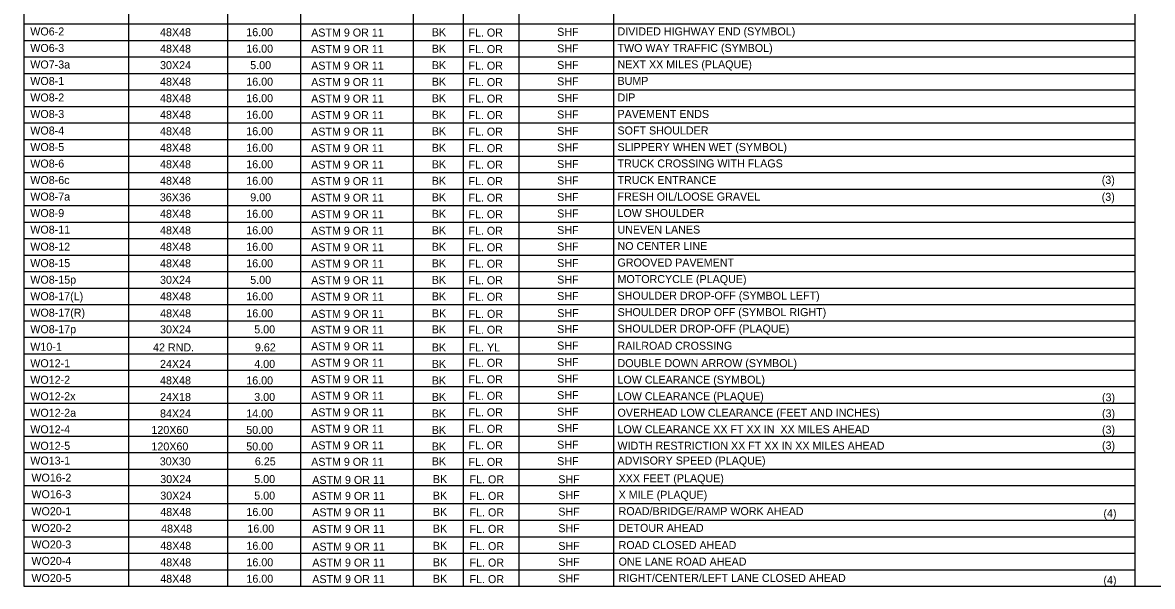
# Model space of a CAD drawing. Extents: x -439.1 to -407.9, y -458.1 to -437.7.
# Drawn here: x -439.13 to -418.9, y -458.05 to -447.95 of the extents above; entities that cross this region are included whole.
import ezdxf

# ---------------------------------------------------------------- set-up
doc = ezdxf.new("R2010")
doc.units = 0
for name, color, linetype in [('Draft_Named_Boundary', 7, 'Continuous'), ('Level 4', 7, 'Continuous'), ('Level 45', 7, 'Continuous')]:
    doc.layers.add(name, color=color, linetype=linetype)

msp = doc.modelspace()

# ---------------------------------------------------------------- linework, layer by layer
at = {"layer": 'Draft_Named_Boundary'}
msp.add_lwpolyline([(-439.109, -458.051), (-407.859, -458.051), (-407.859, -437.676), (-439.109, -437.676)], close=True, dxfattribs=at)
at = {"layer": 'Level 4'}
for p, q in [((-439.109, -437.676), (-439.109, -458.051)), ((-419.212, -437.676), (-419.212, -458.051)), ((-437.233, -438.806), (-437.233, -458.051)), ((-435.462, -438.806), (-435.462, -458.051)), ((-434.152, -438.806), (-434.152, -458.051)), ((-432.136, -438.806), (-432.136, -458.051)), ((-431.24, -438.806), (-431.24, -458.051)), ((-430.244, -438.806), (-430.244, -458.051)), ((-428.547, -438.806), (-428.547, -458.051)), ((-439.109, -447.976), (-419.212, -447.976)), ((-439.109, -448.272), (-419.212, -448.272)), ((-439.109, -448.568), (-419.212, -448.568)), ((-439.109, -448.864), (-419.212, -448.864)), ((-439.109, -449.159), (-419.212, -449.159)), ((-439.109, -449.455), (-419.212, -449.455)), ((-439.109, -449.751), (-419.212, -449.751)), ((-439.109, -450.047), (-419.212, -450.047)), ((-439.109, -450.343), (-419.212, -450.343)), ((-439.109, -450.638), (-419.212, -450.638)), ((-439.109, -450.934), (-419.212, -450.934)), ((-439.109, -451.23), (-419.212, -451.23)), ((-439.109, -451.526), (-419.212, -451.526)), ((-439.109, -451.822), (-419.212, -451.822)), ((-439.109, -452.117), (-419.212, -452.117)), ((-439.109, -452.413), (-419.212, -452.413)), ((-439.109, -452.709), (-419.212, -452.709)), ((-439.109, -453.005), (-419.212, -453.005)), ((-439.109, -453.298), (-419.212, -453.298)), ((-439.109, -453.591), (-419.212, -453.591)), ((-439.109, -453.885), (-419.212, -453.885)), ((-439.109, -454.178), (-419.212, -454.178)), ((-439.109, -454.474), (-419.212, -454.474)), ((-439.109, -454.769), (-419.212, -454.769)), ((-439.109, -455.065), (-419.212, -455.065)), ((-439.109, -455.361), (-419.212, -455.361)), ((-439.109, -455.656), (-419.212, -455.656)), ((-439.109, -455.952), (-419.212, -455.952)), ((-439.109, -456.248), (-419.212, -456.248)), ((-439.109, -456.571), (-419.212, -456.571)), ((-439.129, -456.867), (-419.232, -456.867)), ((-439.109, -457.163), (-419.212, -457.163)), ((-439.109, -457.458), (-419.212, -457.458)), ((-439.109, -457.754), (-419.212, -457.754)), ((-439.109, -458.051), (-419.212, -458.051))]:
    msp.add_line(p, q, dxfattribs=at)

# ---------------------------------------------------------------- texts
for s, height, p in [('WO6-2', 0.1433, (-438.991, -448.183)), ('ASTM 9 OR 11', 0.14328, (-433.962, -448.203)), ('BK', 0.1433, (-431.802, -448.196)), ('FL. OR', 0.1433, (-431.146, -448.203)), ('SHF', 0.1433, (-429.557, -448.19)), ('DIVIDED HIGHWAY END (SYMBOL)', 0.14328, (-428.477, -448.182)), ('WO6-3', 0.1433, (-438.991, -448.479)), ('ASTM 9 OR 11', 0.14328, (-433.962, -448.499)), ('BK', 0.1433, (-431.802, -448.491)), ('FL. OR', 0.1433, (-431.146, -448.499)), ('SHF', 0.1433, (-429.557, -448.486)), ('TWO WAY TRAFFIC (SYMBOL)', 0.14328, (-428.477, -448.478)), ('WO7-3a', 0.1433, (-438.991, -448.775)), ('ASTM 9 OR 11', 0.14328, (-433.962, -448.795)), ('BK', 0.1433, (-431.802, -448.787)), ('FL. OR', 0.1433, (-431.146, -448.795)), ('SHF', 0.1433, (-429.557, -448.782)), ('NEXT XX MILES (PLAQUE)', 0.14328, (-428.477, -448.773)), ('WO8-1 ', 0.1433, (-438.991, -449.071)), ('ASTM 9 OR 11', 0.14328, (-433.962, -449.09)), ('BK', 0.1433, (-431.802, -449.083)), ('FL. OR', 0.1433, (-431.146, -449.091)), ('SHF', 0.1433, (-429.557, -449.078)), ('BUMP', 0.1433, (-428.477, -449.069)), ('WO8-2 ', 0.1433, (-438.991, -449.366)), ('ASTM 9 OR 11', 0.14328, (-433.962, -449.386)), ('BK', 0.1433, (-431.802, -449.379)), ('FL. OR', 0.1433, (-431.146, -449.386)), ('SHF', 0.1433, (-429.557, -449.374)), ('DIP', 0.1433, (-428.477, -449.365)), ('WO8-3', 0.1433, (-438.991, -449.662)), ('ASTM 9 OR 11', 0.14328, (-433.962, -449.682)), ('BK', 0.1433, (-431.802, -449.675)), ('FL. OR', 0.1433, (-431.146, -449.682)), ('SHF', 0.1433, (-429.557, -449.67)), ('PAVEMENT ENDS', 0.14328, (-428.477, -449.661)), ('WO8-4 ', 0.1433, (-438.991, -449.958)), ('ASTM 9 OR 11', 0.14328, (-433.962, -449.978)), ('BK', 0.1433, (-431.802, -449.97)), ('FL. OR', 0.1433, (-431.146, -449.978)), ('SHF', 0.1433, (-429.557, -449.965)), ('SOFT SHOULDER', 0.14328, (-428.477, -449.957)), ('SLIPPERY WHEN WET (SYMBOL) ', 0.14328, (-428.477, -450.253)), ('WO8-5 ', 0.1433, (-438.991, -450.254)), ('ASTM 9 OR 11', 0.14328, (-433.962, -450.274)), ('BK', 0.1433, (-431.802, -450.266)), ('FL. OR', 0.1433, (-431.146, -450.274)), ('SHF', 0.1433, (-429.557, -450.261)), ('WO8-6 ', 0.1433, (-438.991, -450.55)), ('ASTM 9 OR 11', 0.14328, (-433.962, -450.569)), ('BK', 0.1433, (-431.802, -450.562)), ('FL. OR', 0.1433, (-431.146, -450.57)), ('SHF', 0.1433, (-429.557, -450.557)), ('TRUCK CROSSING WITH FLAGS', 0.14328, (-428.477, -450.548)), ('WO8-6c', 0.1433, (-438.991, -450.845)), ('BK', 0.1433, (-431.802, -450.858)), ('SHF', 0.1433, (-429.557, -450.853)), ('TRUCK ENTRANCE ', 0.14328, (-428.477, -450.844)), ('(3)', 0.1433, (-419.806, -450.842)), ('ASTM 9 OR 11', 0.14328, (-433.962, -450.865)), ('FL. OR', 0.1433, (-431.146, -450.865)), ('WO8-7a ', 0.1433, (-438.991, -451.141)), ('ASTM 9 OR 11', 0.14328, (-433.962, -451.161)), ('BK', 0.1433, (-431.802, -451.154)), ('FL. OR', 0.1433, (-431.146, -451.161)), ('SHF', 0.1433, (-429.557, -451.149)), ('FRESH OIL/LOOSE GRAVEL', 0.14328, (-428.477, -451.14)), ('(3)', 0.1433, (-419.807, -451.146)), ('WO8-9', 0.1433, (-438.991, -451.437)), ('ASTM 9 OR 11', 0.14328, (-433.962, -451.457)), ('BK', 0.1433, (-431.802, -451.45)), ('FL. OR', 0.1433, (-431.146, -451.457)), ('SHF', 0.1433, (-429.557, -451.444)), ('LOW SHOULDER', 0.14328, (-428.477, -451.436)), ('WO8-11', 0.1433, (-438.991, -451.733)), ('ASTM 9 OR 11', 0.14328, (-433.962, -451.753)), ('BK', 0.1433, (-431.802, -451.745)), ('FL. OR', 0.1433, (-431.146, -451.753)), ('SHF', 0.1433, (-429.557, -451.74)), ('UNEVEN LANES', 0.14328, (-428.477, -451.732)), ('WO8-12', 0.1433, (-438.991, -452.038)), ('ASTM 9 OR 11', 0.14328, (-433.962, -452.049)), ('BK', 0.1433, (-431.802, -452.041)), ('FL. OR', 0.1433, (-431.146, -452.049)), ('SHF', 0.1433, (-429.557, -452.036)), ('NO CENTER LINE', 0.14328, (-428.477, -452.027)), ('WO8-15', 0.1433, (-438.991, -452.334)), ('ASTM 9 OR 11', 0.14328, (-433.962, -452.344)), ('BK', 0.1433, (-431.802, -452.337)), ('FL. OR', 0.1433, (-431.146, -452.344)), ('SHF', 0.1433, (-429.557, -452.332)), ('GROOVED PAVEMENT', 0.14328, (-428.477, -452.323)), ('WO8-15p', 0.1433, (-438.991, -452.63)), ('ASTM 9 OR 11', 0.14328, (-433.962, -452.64)), ('BK', 0.1433, (-431.802, -452.633)), ('FL. OR', 0.1433, (-431.146, -452.64)), ('SHF', 0.1433, (-429.557, -452.628)), ('MOTORCYCLE (PLAQUE)', 0.14328, (-428.477, -452.619)), ('WO8-17(L)', 0.1433, (-438.991, -452.926)), ('ASTM 9 OR 11', 0.14328, (-433.962, -452.936)), ('BK', 0.1433, (-431.802, -452.929)), ('FL. OR', 0.1433, (-431.146, -452.936)), ('SHF', 0.1433, (-429.557, -452.923)), ('SHOULDER DROP-OFF (SYMBOL LEFT)', 0.14328, (-428.477, -452.915)), ('WO8-17(R)', 0.1433, (-438.99, -453.221)), ('ASTM 9 OR 11', 0.14328, (-433.961, -453.242)), ('BK', 0.1433, (-431.8, -453.233)), ('FL. OR', 0.1433, (-431.144, -453.242)), ('SHF', 0.1433, (-429.556, -453.229)), ('SHOULDER DROP OFF (SYMBOL RIGHT)', 0.14328, (-428.476, -453.211)), ('WO8-17p', 0.1433, (-438.991, -453.517)), ('ASTM 9 OR 11', 0.14328, (-433.962, -453.527)), ('BK', 0.1433, (-431.802, -453.52)), ('FL. OR', 0.1433, (-431.146, -453.527)), ('SHF', 0.1433, (-429.557, -453.515)), ('SHOULDER DROP-OFF (PLAQUE)', 0.14328, (-428.477, -453.506)), ('W10-1', 0.1433, (-438.991, -453.831)), ('ASTM 9 OR 11', 0.14328, (-433.962, -453.823)), ('BK', 0.1433, (-431.802, -453.843)), ('FL. YL', 0.1433, (-431.142, -453.843)), ('SHF', 0.1433, (-429.557, -453.81)), ('RAILROAD CROSSING', 0.14328, (-428.477, -453.814)), ('WO12-1', 0.1433, (-438.991, -454.127)), ('ASTM 9 OR 11', 0.14328, (-433.962, -454.119)), ('BK', 0.1433, (-431.802, -454.139)), ('FL. OR', 0.1433, (-431.146, -454.119)), ('SHF', 0.1433, (-429.557, -454.106)), ('DOUBLE DOWN ARROW (SYMBOL)', 0.14328, (-428.477, -454.125)), ('WO12-2 ', 0.1433, (-438.991, -454.423)), ('ASTM 9 OR 11', 0.14328, (-433.962, -454.414)), ('BK', 0.1433, (-431.802, -454.435)), ('FL. OR', 0.1433, (-431.146, -454.415)), ('SHF', 0.1433, (-429.557, -454.402)), ('LOW CLEARANCE (SYMBOL)', 0.14328, (-428.477, -454.421)), ('SHF', 0.1433, (-429.557, -454.698)), ('WO12-2x', 0.1433, (-438.991, -454.718)), ('ASTM 9 OR 11', 0.14328, (-433.962, -454.71)), ('BK', 0.1433, (-431.802, -454.731)), ('FL. OR', 0.1433, (-431.146, -454.71)), ('LOW CLEARANCE (PLAQUE)', 0.14328, (-428.477, -454.717)), ('(3)', 0.1433, (-419.802, -454.738)), ('WO12-2a', 0.1433, (-438.991, -455.014)), ('ASTM 9 OR 11', 0.14328, (-433.962, -455.006)), ('BK', 0.1433, (-431.802, -455.027)), ('FL. OR', 0.1433, (-431.146, -455.006)), ('SHF', 0.1433, (-429.557, -454.994)), ('OVERHEAD LOW CLEARANCE (FEET AND INCHES)', 0.14328, (-428.477, -455.013)), ('(3)', 0.1433, (-419.802, -455.025)), ('WO12-4', 0.1433, (-438.991, -455.31)), ('ASTM 9 OR 11', 0.14328, (-433.962, -455.302)), ('FL. OR', 0.1433, (-431.146, -455.302)), ('SHF', 0.1433, (-429.557, -455.289)), ('LOW CLEARANCE XX FT XX IN  XX MILES AHEAD', 0.14328, (-428.477, -455.309)), ('BK', 0.1433, (-431.802, -455.322)), ('(3)', 0.1433, (-419.802, -455.317)), ('WO12-5', 0.1433, (-438.991, -455.606)), ('ASTM 9 OR 11', 0.14328, (-433.962, -455.598)), ('BK', 0.1433, (-431.802, -455.618)), ('FL. OR', 0.1433, (-431.146, -455.598)), ('SHF', 0.1433, (-429.557, -455.585)), ('WIDTH RESTRICTION XX FT XX IN XX MILES AHEAD', 0.14328, (-428.477, -455.604)), ('(3)', 0.1433, (-419.802, -455.6)), ('WO13-1 ', 0.1433, (-438.991, -455.871)), ('ASTM 9 OR 11', 0.14328, (-433.962, -455.893)), ('BK', 0.1433, (-431.802, -455.884)), ('FL. OR', 0.1433, (-431.146, -455.894)), ('SHF', 0.1433, (-429.557, -455.881)), ('ADVISORY SPEED (PLAQUE)', 0.14328, (-428.477, -455.87)), ('WO16-2', 0.1433, (-438.971, -456.177)), ('ASTM 9 OR 11', 0.14328, (-433.942, -456.217)), ('BK', 0.1433, (-431.782, -456.202)), ('FL. OR', 0.1433, (-431.126, -456.207)), ('SHF', 0.1433, (-429.537, -456.205)), ('XXX FEET (PLAQUE)', 0.14328, (-428.457, -456.188)), ('WO16-3', 0.1433, (-438.971, -456.473)), ('ASTM 9 OR 11', 0.14328, (-433.942, -456.503)), ('BK', 0.1433, (-431.782, -456.498)), ('FL. OR', 0.1433, (-431.126, -456.503)), ('SHF', 0.1433, (-429.537, -456.49)), ('X MILE (PLAQUE)', 0.14328, (-428.457, -456.484)), ('WO20-1', 0.1433, (-438.971, -456.778)), ('ASTM 9 OR 11', 0.14328, (-433.942, -456.798)), ('BK', 0.1433, (-431.782, -456.791)), ('FL. OR', 0.1433, (-431.126, -456.799)), ('SHF', 0.1433, (-429.537, -456.786)), ('ROAD/BRIDGE/RAMP WORK AHEAD ', 0.14328, (-428.457, -456.777)), ('(4)', 0.1433, (-419.776, -456.815)), ('WO20-2', 0.1433, (-438.971, -457.077)), ('ASTM 9 OR 11', 0.14328, (-433.942, -457.094)), ('BK', 0.1433, (-431.782, -457.089)), ('FL. OR', 0.1433, (-431.126, -457.094)), ('SHF', 0.1433, (-429.537, -457.082)), ('DETOUR AHEAD', 0.14328, (-428.457, -457.076)), ('WO20-3', 0.1433, (-438.971, -457.373)), ('ASTM 9 OR 11', 0.14328, (-433.942, -457.413)), ('BK', 0.1433, (-431.782, -457.398)), ('FL. OR', 0.1433, (-431.126, -457.403)), ('SHF', 0.1433, (-429.537, -457.4)), ('ROAD CLOSED AHEAD', 0.14328, (-428.457, -457.384)), ('WO20-4', 0.1433, (-438.971, -457.668)), ('ASTM 9 OR 11', 0.14328, (-433.942, -457.698)), ('BK', 0.1433, (-431.782, -457.693)), ('FL. OR', 0.1433, (-431.126, -457.698)), ('SHF', 0.1433, (-429.537, -457.686)), ('ONE LANE ROAD AHEAD', 0.14328, (-428.457, -457.68)), ('WO20-5', 0.1433, (-438.971, -457.974)), ('ASTM 9 OR 11', 0.14328, (-433.942, -457.994)), ('BK', 0.1433, (-431.782, -457.987)), ('FL. OR', 0.1433, (-431.126, -457.994)), ('SHF', 0.1433, (-429.537, -457.982)), ('RIGHT/CENTER/LEFT LANE CLOSED AHEAD ', 0.14328, (-428.457, -457.973)), ('(4)', 0.1433, (-419.776, -458.01))]:
    msp.add_text(s, height=height, dxfattribs=at).set_placement(p)
at = {"layer": 'Level 45'}
for s, p in [('48X48', (-436.668, -448.196)), ('16.00', (-435.124, -448.196)), ('48X48', (-436.668, -448.491)), ('16.00', (-435.124, -448.491)), ('30X24', (-436.668, -448.787)), ('5.00', (-435.053, -448.787)), ('48X48', (-436.668, -449.083)), ('16.00', (-435.124, -449.083)), ('48X48', (-436.668, -449.379)), ('16.00', (-435.124, -449.379)), ('48X48', (-436.668, -449.675)), ('16.00', (-435.124, -449.675)), ('48X48', (-436.668, -449.97)), ('16.00', (-435.124, -449.97)), ('48X48', (-436.668, -450.266)), ('16.00', (-435.124, -450.266)), ('48X48', (-436.668, -450.562)), ('16.00', (-435.124, -450.562)), ('48X48', (-436.668, -450.858)), ('16.00', (-435.124, -450.858)), ('36X36', (-436.671, -451.154)), ('9.00', (-435.053, -451.154)), ('48X48', (-436.668, -451.45)), ('16.00', (-435.124, -451.45)), ('48X48', (-436.668, -451.745)), ('16.00', (-435.124, -451.745)), ('48X48', (-436.668, -452.041)), ('16.00', (-435.124, -452.041)), ('48X48', (-436.668, -452.337)), ('16.00', (-435.124, -452.337)), ('30X24', (-436.668, -452.633)), ('5.00', (-435.053, -452.633)), ('48X48', (-436.668, -452.929)), ('16.00', (-435.124, -452.929)), ('48X48', (-436.666, -453.233)), ('16.00', (-435.123, -453.233)), ('30X24', (-436.668, -453.52)), ('5.00', (-434.981, -453.52)), ('42 RND.', (-436.793, -453.843)), ('9.62', (-434.969, -453.843)), ('24X24', (-436.668, -454.139)), ('4.00', (-434.981, -454.139)), ('48X48', (-436.668, -454.435)), ('16.00', (-435.124, -454.435)), ('24X18', (-436.668, -454.731)), ('3.00', (-434.981, -454.731)), ('84X24', (-436.668, -455.027)), ('14.00', (-435.124, -455.027)), ('120X60', (-436.822, -455.322)), ('50.00', (-435.124, -455.322)), ('120X60', (-436.822, -455.618)), ('50.00', (-435.124, -455.618)), ('30X30', (-436.673, -455.884)), ('6.25', (-434.97, -455.884)), ('30X24', (-436.664, -456.202)), ('5.00', (-434.981, -456.202)), ('30X24', (-436.664, -456.498)), ('5.00', (-434.981, -456.498)), ('48X48', (-436.664, -456.791)), ('16.00', (-435.121, -456.791)), ('48X48', (-436.648, -457.089)), ('16.00', (-435.104, -457.089)), ('48X48', (-436.664, -457.398)), ('16.00', (-435.121, -457.398)), ('48X48', (-436.664, -457.693)), ('16.00', (-435.121, -457.693)), ('48X48', (-436.664, -457.987)), ('16.00', (-435.121, -457.987))]:
    msp.add_text(s, height=0.1433, dxfattribs=at).set_placement(p)

doc.saveas('drawing.dxf')
